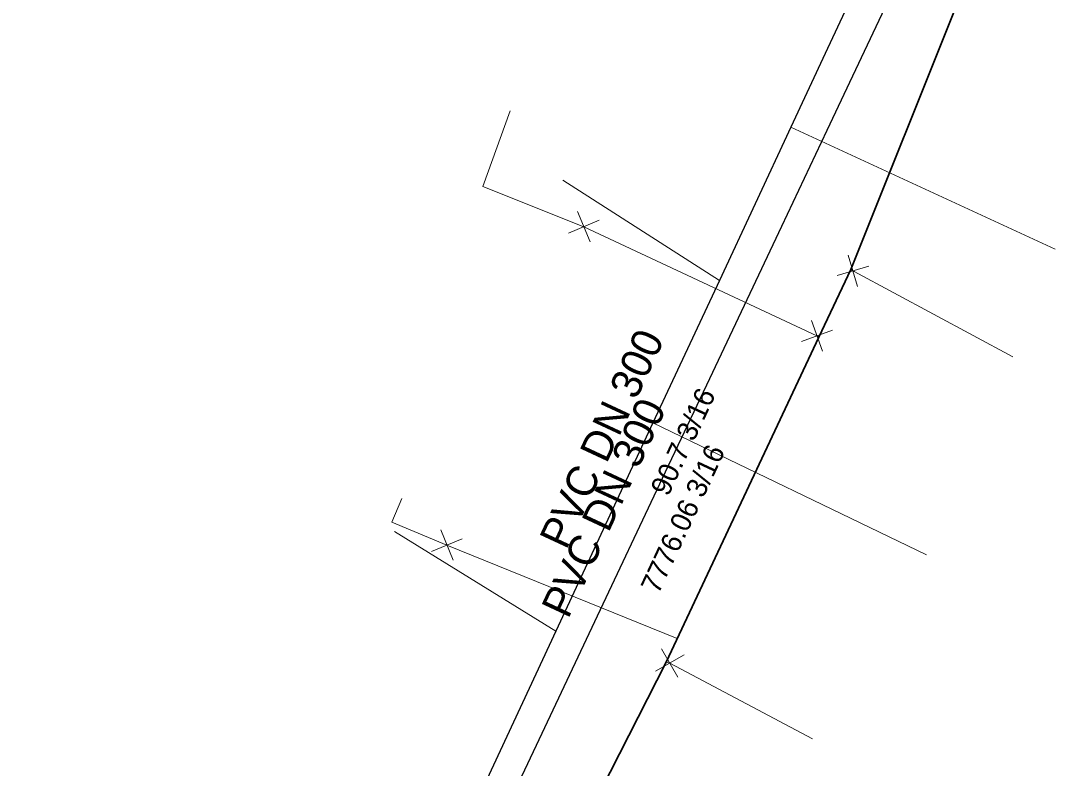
# Model space of a CAD drawing. Extents: x -772952 to -772403, y -1033777 to -1033210.
# Drawn here: x -772870.4 to -772829.72, y -1033532.28 to -1033502.87 of the extents above; entities that cross this region are included whole.
import ezdxf

# ---------------------------------------------------------------- set-up
doc = ezdxf.new("R2010")
doc.units = 0
doc.header["$LTSCALE"] = 0.36
for name, color, linetype, lineweight in [('15', 7, 'Continuous', 13), ('16', 7, 'Continuous', 35), ('2', 7, 'Continuous', 25), ('57', 7, 'Continuous', 13), ('59', 7, 'Continuous', 13)]:
    doc.layers.add(name, color=color, linetype=linetype, lineweight=lineweight)
doc.layers.add('3', color=7, linetype='Continuous')

msp = doc.modelspace()

# ---------------------------------------------------------------- linework, layer by layer
at = {"layer": '15'}
for p, q in [((-772848.007, -1033511.572), (-772848.512, -1033510.384)), ((-772847.662, -1033510.724), (-772848.859, -1033511.236)), ((-772837.859, -1033512.093), (-772837.493, -1033513.331)), ((-772838.298, -1033512.896), (-772837.05, -1033512.524)), ((-772838.872, -1033515.875), (-772839.309, -1033514.661)), ((-772838.48, -1033515.049), (-772839.704, -1033515.491)), ((-772853.398, -1033524.099), (-772853.886, -1033522.905)), ((-772853.042, -1033523.257), (-772854.246, -1033523.752)), ((-772845.204, -1033527.582), (-772844.563, -1033528.702)), ((-772845.447, -1033528.464), (-772844.318, -1033527.815))]:
    msp.add_line(p, q, dxfattribs=at)
at = {"layer": '16'}
msp.add_lwpolyline([(-772870.403, -1033572.723), (-772865.918, -1033565.594), (-772858.208, -1033552.52), (-772854.394, -1033546.056), (-772851.153, -1033540.157), (-772849.795, -1033537.486), (-772845.024, -1033528.103), (-772839.019, -1033515.318), (-772837.765, -1033512.662), (-772833.548, -1033502.146)], dxfattribs=at)
at = {"layer": '2'}
for points in [[(-772834.78, -1033495.6), (-772836.114, -1033498.463), (-772837.51, -1033501.461), (-772838.768, -1033504.161), (-772840.12, -1033507.062), (-772842.931, -1033513.095), (-772845.54, -1033518.695), (-772849.358, -1033526.891), (-772852.073, -1033532.717), (-772853.674, -1033536.155), (-772854.426, -1033537.769), (-772855.508, -1033540.092), (-772855.782, -1033540.679), (-772856.3, -1033541.79)], [(-772834.12, -1033497.489), (-772836.663, -1033502.872), (-772837.696, -1033505.057), (-772838.705, -1033507.192), (-772840.489, -1033510.965), (-772843.322, -1033516.96), (-772845.177, -1033520.885), (-772847.84, -1033526.52), (-772850.14, -1033531.386), (-772853.138, -1033537.728), (-772854.606, -1033540.835), (-772856.75, -1033545.37)]]:
    msp.add_lwpolyline(points, dxfattribs=at)
at = {"layer": '57'}
for p, q in [((-772840.12, -1033507.062), (-772829.72, -1033511.86)), ((-772842.931, -1033513.095), (-772849.09, -1033509.15)), ((-772845.54, -1033518.695), (-772834.78, -1033523.89)), ((-772849.358, -1033526.891), (-772855.71, -1033522.96))]:
    msp.add_line(p, q, dxfattribs=at)
at = {"layer": '59'}
for points in [[(-772839.02, -1033515.319), (-772839.091, -1033515.271), (-772848.26, -1033510.98), (-772852.23, -1033509.39), (-772851.16, -1033506.42)], [(-772837.766, -1033512.663), (-772837.628, -1033512.736), (-772831.393, -1033516.1)], [(-772844.59, -1033527.177), (-772853.643, -1033523.504), (-772855.809, -1033522.601), (-772855.416, -1033521.669)], [(-772845.025, -1033528.103), (-772844.884, -1033528.141), (-772839.264, -1033531.117)]]:
    msp.add_lwpolyline(points, dxfattribs=at)

# ---------------------------------------------------------------- texts
at = {"layer": '3'}
for s, height, p in [('PVC DN 300', 1.2, (-772848.953, -1033523.722)), ('90.7 3/16', 0.8, (-772844.942, -1033521.619)), ('PVC DN 300', 1.2, (-772848.877, -1033526.44)), ('7776.06 3/16 ', 0.8, (-772845.327, -1033525.461))]:
    msp.add_text(s, height=height, rotation=65, dxfattribs=at).set_placement(p)

doc.saveas('drawing.dxf')
